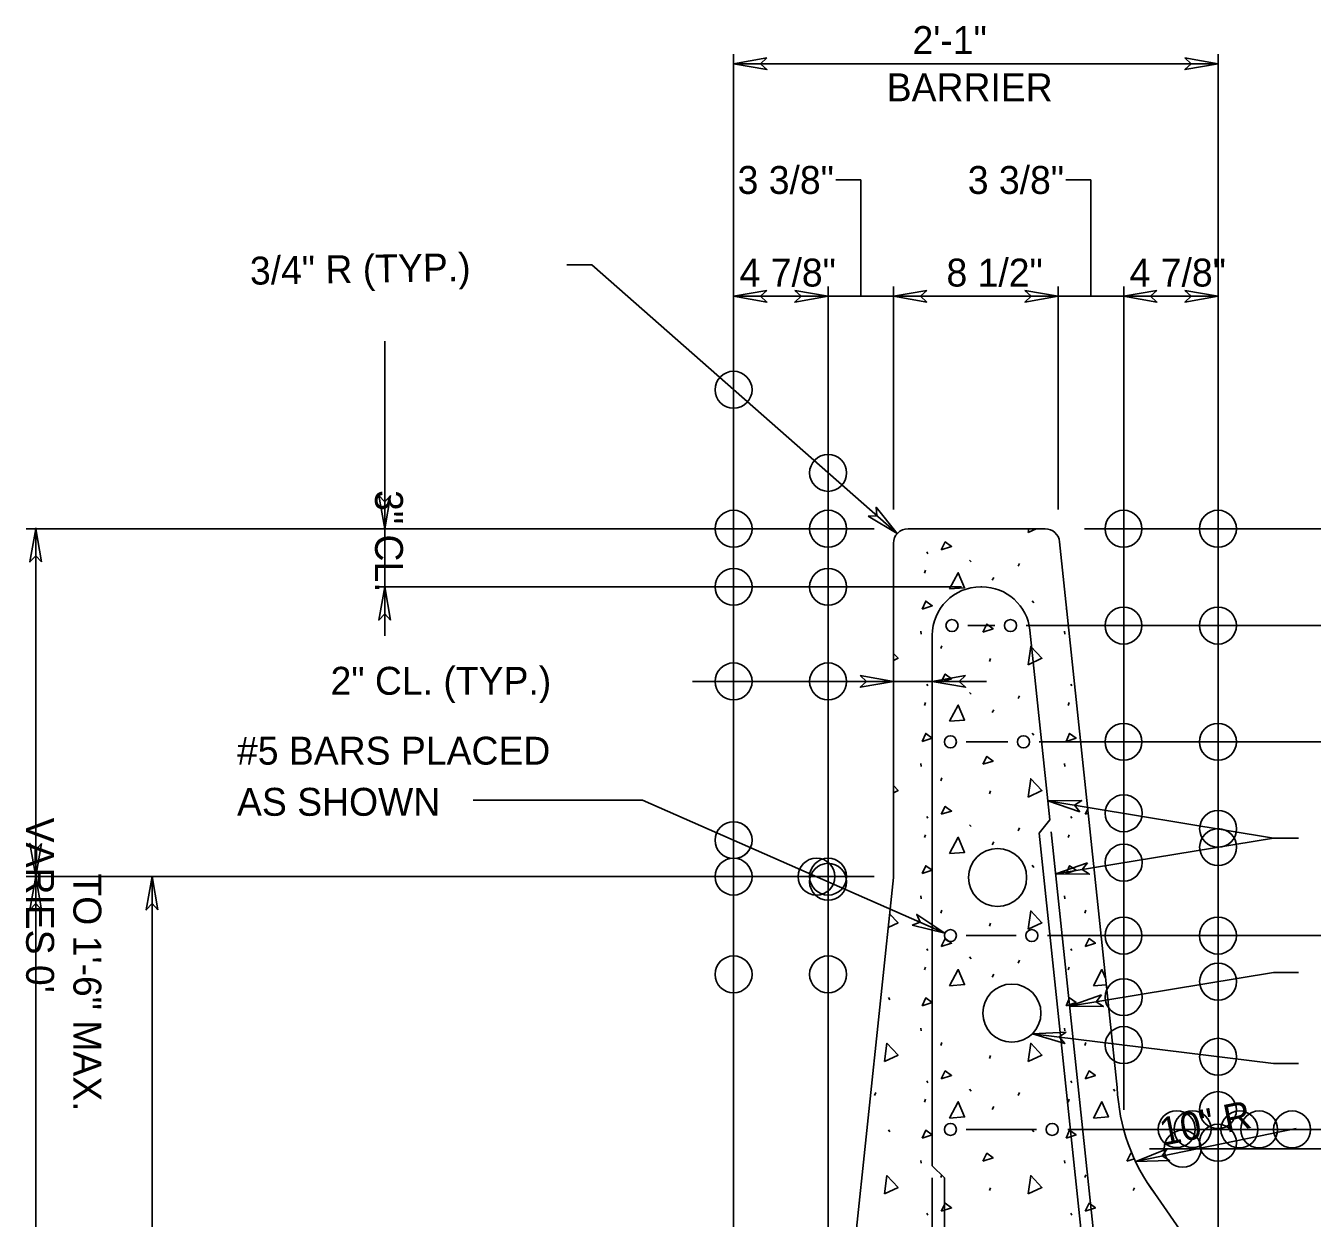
# Model space of a CAD drawing. Extents: x -26.46 to -19.21, y -3.62 to 6.25.
# Drawn here: x -25.012 to -22.246, y 3.682 to 6.246 of the extents above; entities that cross this region are included whole.
import ezdxf

# ---------------------------------------------------------------- set-up
doc = ezdxf.new("R2010")
doc.units = 0
for name, color, linetype in [('ANNO-WOUT', 7, 'Continuous'), ('CABLE_RUN', 7, 'Continuous'), ('DETL-DIMS', 7, 'Continuous'), ('DETL-PATT', 7, 'Continuous'), ('Level 10', 7, 'Continuous'), ('Level 12', 7, 'Continuous'), ('SUPR-PARA_P', 7, 'Continuous'), ('SUPR-RFRC', 7, 'Continuous')]:
    doc.layers.add(name, color=color, linetype=linetype)

msp = doc.modelspace()

# ---------------------------------------------------------------- linework, layer by layer
at = {"layer": 'ANNO-WOUT'}
for centre in [(-23.4904, 5.4635), (-23.2873, 5.2847), (-23.4904, 5.1646), (-23.2873, 5.1646), (-22.6522, 5.1646), (-22.4491, 5.1646), (-23.4904, 5.0396), (-23.2873, 5.0396), (-22.6522, 4.9563), (-22.4491, 4.9563), (-23.4904, 4.8363), (-23.2873, 4.8363), (-22.6522, 4.7063), (-22.4491, 4.7063), (-22.6518, 4.5526), (-22.4488, 4.5192), (-23.4904, 4.4949), (-23.4903, 4.4949), (-22.4488, 4.4799), (-22.6518, 4.4465), (-23.4904, 4.4164), (-23.3122, 4.4164), (-23.2873, 4.4164), (-23.2873, 4.4054), (-22.6522, 4.2896), (-22.4491, 4.2896), (-23.4904, 4.2063), (-23.2873, 4.2063), (-22.4488, 4.1906), (-22.6518, 4.1572), (-22.6518, 4.0543), (-22.4488, 4.0291), (-22.4491, 3.9144), (-22.5378, 3.8734), (-22.5037, 3.8734), (-22.403, 3.8729), (-22.3606, 3.8729), (-22.2898, 3.8729), (-22.4491, 3.8442), (-22.5251, 3.8313)]:
    msp.add_circle(centre, 0.0397, dxfattribs=at)
at = {"layer": 'CABLE_RUN'}
for centre in [(-22.9229, 4.4146), (-22.8922, 4.1229)]:
    msp.add_circle(centre, 0.0625, dxfattribs=at)
at = {"layer": 'DETL-DIMS'}
for p, q in [((-23.4904, 6.1646), (-23.419, 6.1771)), ((-23.419, 6.1771), (-23.4324, 6.1646)), ((-22.4488, 6.1646), (-22.5203, 6.1771)), ((-22.5203, 6.1771), (-22.5068, 6.1646)), ((-23.4904, 6.1646), (-23.4189, 6.1519)), ((-23.4324, 6.1646), (-23.4189, 6.1519)), ((-22.4488, 6.1646), (-22.5203, 6.1519)), ((-22.5068, 6.1646), (-22.5203, 6.1519)), ((-23.4904, 5.6646), (-23.419, 5.6771)), ((-23.419, 5.6771), (-23.4324, 5.6646)), ((-23.2873, 5.6646), (-23.3588, 5.6771)), ((-23.3588, 5.6771), (-23.3453, 5.6646)), ((-23.1467, 5.6646), (-23.0752, 5.6771)), ((-23.0752, 5.6771), (-23.0887, 5.6646)), ((-22.7925, 5.6646), (-22.864, 5.6771)), ((-22.864, 5.6771), (-22.8505, 5.6646)), ((-22.6519, 5.6646), (-22.5804, 5.6771)), ((-22.5804, 5.6771), (-22.5939, 5.6646)), ((-22.4488, 5.6646), (-22.5203, 5.6771)), ((-22.5203, 5.6771), (-22.5068, 5.6646)), ((-23.4904, 5.6646), (-23.4189, 5.6519)), ((-23.4324, 5.6646), (-23.4189, 5.6519)), ((-23.2873, 5.6646), (-23.3588, 5.6519)), ((-23.3453, 5.6646), (-23.3588, 5.6519)), ((-23.1467, 5.6646), (-23.0752, 5.6519)), ((-23.0887, 5.6646), (-23.0752, 5.6519)), ((-22.7925, 5.6646), (-22.8641, 5.6519)), ((-22.8505, 5.6646), (-22.8641, 5.6519)), ((-22.6519, 5.6646), (-22.5804, 5.6519)), ((-22.5939, 5.6646), (-22.5804, 5.6519)), ((-22.4488, 5.6646), (-22.5203, 5.6519)), ((-22.5068, 5.6646), (-22.5203, 5.6519)), ((-24.2404, 5.1646), (-24.2531, 5.2361)), ((-24.2404, 5.2226), (-24.2531, 5.2361)), ((-24.2404, 5.1646), (-24.2279, 5.2361)), ((-24.2279, 5.2361), (-24.2404, 5.2226)), ((-23.1389, 5.154), (-23.1842, 5.2108)), ((-23.1824, 5.1923), (-23.1842, 5.2108)), ((-23.2008, 5.1919), (-23.1824, 5.1923)), ((-23.1389, 5.154), (-23.2008, 5.1919)), ((-24.9904, 5.1646), (-25.0031, 5.0931)), ((-24.9904, 5.1646), (-24.9779, 5.0931)), ((-24.9904, 5.1066), (-25.0031, 5.0931)), ((-24.9779, 5.0931), (-24.9904, 5.1066)), ((-24.2404, 5.0396), (-24.2531, 4.9681)), ((-24.2404, 5.0396), (-24.2279, 4.9681)), ((-24.2404, 4.9816), (-24.2531, 4.9681)), ((-24.2279, 4.9681), (-24.2404, 4.9816)), ((-23.1467, 4.8363), (-23.2182, 4.8488)), ((-23.2182, 4.8488), (-23.2047, 4.8363)), ((-23.0634, 4.8363), (-22.9919, 4.8488)), ((-22.9919, 4.8488), (-23.0054, 4.8363)), ((-23.1467, 4.8363), (-23.2182, 4.8236)), ((-23.2047, 4.8363), (-23.2182, 4.8236)), ((-23.0634, 4.8363), (-22.9918, 4.8236)), ((-23.0054, 4.8363), (-22.9918, 4.8236)), ((-22.8146, 4.5795), (-22.742, 4.5804)), ((-22.8146, 4.5795), (-22.7461, 4.5555)), ((-22.7574, 4.57), (-22.742, 4.5804)), ((-22.7461, 4.5555), (-22.7574, 4.57)), ((-24.9904, 4.4164), (-25.0031, 4.4879)), ((-24.9904, 4.4744), (-25.0031, 4.4879)), ((-24.9904, 4.4164), (-24.9779, 4.4879)), ((-24.9779, 4.4879), (-24.9904, 4.4744)), ((-22.798, 4.4224), (-22.7295, 4.4463)), ((-22.7295, 4.4463), (-22.7408, 4.4318)), ((-22.7408, 4.4318), (-22.7254, 4.4215)), ((-24.9904, 4.4164), (-25.0031, 4.3449)), ((-24.9904, 4.4164), (-24.9779, 4.3449)), ((-24.7404, 4.4164), (-24.7531, 4.3449)), ((-24.7404, 4.4164), (-24.7279, 4.3449)), ((-22.798, 4.4224), (-22.7254, 4.4215)), ((-24.9904, 4.3584), (-25.0031, 4.3449)), ((-24.9779, 4.3449), (-24.9904, 4.3584)), ((-24.7404, 4.3584), (-24.7531, 4.3449)), ((-24.7279, 4.3449), (-24.7404, 4.3584)), ((-23.1067, 4.3122), (-23.0893, 4.3182)), ((-23.0362, 4.2948), (-23.0965, 4.3353)), ((-23.0893, 4.3182), (-23.0965, 4.3353)), ((-23.0362, 4.2948), (-23.1067, 4.3122)), ((-22.768, 4.138), (-22.6995, 4.162)), ((-22.6995, 4.162), (-22.7108, 4.1474)), ((-22.768, 4.138), (-22.6954, 4.1371)), ((-22.7108, 4.1474), (-22.6954, 4.1371)), ((-22.848, 4.0787), (-22.7755, 4.0823)), ((-22.848, 4.0787), (-22.7786, 4.0573)), ((-22.7755, 4.0823), (-22.7904, 4.0716)), ((-22.7904, 4.0716), (-22.7786, 4.0573)), ((-22.6258, 3.8042), (-22.5583, 3.8308)), ((-22.5583, 3.8308), (-22.569, 3.8158)), ((-22.6258, 3.8042), (-22.5532, 3.8061)), ((-22.569, 3.8158), (-22.5532, 3.8061))]:
    msp.add_line(p, q, dxfattribs=at)
for points in [[(-23.419, 6.1771), (-23.4904, 6.1646), (-23.4189, 6.1519), (-23.4324, 6.1646)], [(-22.5203, 6.1771), (-22.4488, 6.1646), (-22.5203, 6.1519), (-22.5068, 6.1646)], [(-23.419, 5.6771), (-23.4904, 5.6646), (-23.4189, 5.6519), (-23.4324, 5.6646)], [(-23.3588, 5.6771), (-23.2873, 5.6646), (-23.3588, 5.6519), (-23.3453, 5.6646)], [(-23.0752, 5.6771), (-23.1467, 5.6646), (-23.0752, 5.6519), (-23.0887, 5.6646)], [(-22.864, 5.6771), (-22.7925, 5.6646), (-22.8641, 5.6519), (-22.8505, 5.6646)], [(-22.5804, 5.6771), (-22.6519, 5.6646), (-22.5804, 5.6519), (-22.5939, 5.6646)], [(-22.5203, 5.6771), (-22.4488, 5.6646), (-22.5203, 5.6519), (-22.5068, 5.6646)], [(-24.2279, 5.2361), (-24.2404, 5.1646), (-24.2531, 5.2361), (-24.2404, 5.2226)], [(-23.2008, 5.1919), (-23.1389, 5.154), (-23.1842, 5.2108), (-23.1824, 5.1923)], [(-24.9779, 5.0931), (-24.9904, 5.1646), (-25.0031, 5.0931), (-24.9904, 5.1066)], [(-24.2279, 4.9681), (-24.2404, 5.0396), (-24.2531, 4.9681), (-24.2404, 4.9816)], [(-23.2182, 4.8488), (-23.1467, 4.8363), (-23.2182, 4.8236), (-23.2047, 4.8363)], [(-22.9919, 4.8488), (-23.0634, 4.8363), (-22.9918, 4.8236), (-23.0054, 4.8363)], [(-22.7461, 4.5555), (-22.8146, 4.5795), (-22.742, 4.5804), (-22.7574, 4.57)], [(-24.9779, 4.4879), (-24.9904, 4.4164), (-25.0031, 4.4879), (-24.9904, 4.4744)], [(-22.7295, 4.4463), (-22.798, 4.4224), (-22.7254, 4.4215), (-22.7408, 4.4318)], [(-24.9779, 4.3449), (-24.9904, 4.4164), (-25.0031, 4.3449), (-24.9904, 4.3584)], [(-24.7279, 4.3449), (-24.7404, 4.4164), (-24.7531, 4.3449), (-24.7404, 4.3584)], [(-23.1067, 4.3122), (-23.0362, 4.2948), (-23.0965, 4.3353), (-23.0893, 4.3182)], [(-22.6995, 4.162), (-22.768, 4.138), (-22.6954, 4.1371), (-22.7108, 4.1474)], [(-22.7755, 4.0823), (-22.848, 4.0787), (-22.7786, 4.0573), (-22.7904, 4.0716)], [(-22.5583, 3.8308), (-22.6258, 3.8042), (-22.5532, 3.8061), (-22.569, 3.8158)]]:
    msp.add_lwpolyline(points, close=True, dxfattribs=at)
at = {"layer": 'DETL-PATT'}
for p, q in [((-22.9404, 5.1635), (-22.94, 5.1646)), ((-22.8569, 5.1565), (-22.8558, 5.1646)), ((-22.8399, 5.1646), (-22.8569, 5.1565)), ((-23.0749, 5.1148), (-23.0726, 5.1109)), ((-22.9829, 5.097), (-22.9798, 5.0931)), ((-22.8786, 5.0839), (-22.8755, 5.0901)), ((-23.0803, 5.0692), (-23.078, 5.0754)), ((-22.9342, 5.0537), (-22.9311, 5.0599)), ((-22.8484, 5.0097), (-22.8453, 5.005)), ((-22.7758, 4.9919), (-22.7746, 4.9945)), ((-22.7744, 4.9923), (-22.7758, 4.9919)), ((-23.088, 4.944), (-23.0873, 4.9378)), ((-22.7789, 4.944), (-22.7781, 4.9378)), ((-23.0447, 4.9069), (-23.0424, 4.9131)), ((-22.9404, 4.879), (-22.9381, 4.8852)), ((-23.0749, 4.8303), (-23.0726, 4.8265)), ((-22.9829, 4.8126), (-22.9798, 4.8087)), ((-22.7657, 4.8303), (-22.7634, 4.8265)), ((-23.0803, 4.7847), (-23.078, 4.7909)), ((-22.8786, 4.7994), (-22.8755, 4.8056)), ((-22.7711, 4.7847), (-22.7688, 4.7909)), ((-22.9342, 4.7693), (-22.9311, 4.7755)), ((-22.8484, 4.7252), (-22.8453, 4.7206)), ((-23.088, 4.6595), (-23.0873, 4.6533)), ((-22.7789, 4.6595), (-22.7781, 4.6533)), ((-23.0447, 4.6224), (-23.0424, 4.6286)), ((-22.7356, 4.6224), (-22.7354, 4.6229)), ((-22.9404, 4.5946), (-22.9381, 4.6008)), ((-23.0749, 4.5459), (-23.0726, 4.542)), ((-22.7657, 4.5459), (-22.7634, 4.542)), ((-22.7348, 4.5505), (-22.729, 4.5622)), ((-22.728, 4.5527), (-22.7348, 4.5505)), ((-22.9829, 4.5281), (-22.9798, 4.5243)), ((-22.8786, 4.515), (-22.8755, 4.5212)), ((-23.0803, 4.5003), (-23.078, 4.5065)), ((-22.9342, 4.4848), (-22.9311, 4.491)), ((-22.7711, 4.5003), (-22.7688, 4.5065)), ((-22.8484, 4.4408), (-22.8453, 4.4361)), ((-23.088, 4.3751), (-23.0873, 4.3689)), ((-22.7789, 4.3751), (-22.7781, 4.3689)), ((-23.0447, 4.338), (-23.0424, 4.3442)), ((-22.7356, 4.338), (-22.7333, 4.3442)), ((-22.9404, 4.3102), (-22.9381, 4.3163)), ((-23.0749, 4.2615), (-23.0726, 4.2576)), ((-22.7657, 4.2615), (-22.7634, 4.2576)), ((-22.9829, 4.2437), (-22.9798, 4.2398)), ((-22.8786, 4.2305), (-22.8755, 4.2367)), ((-23.0803, 4.2159), (-23.078, 4.222)), ((-22.9342, 4.2004), (-22.9311, 4.2066)), ((-22.7711, 4.2159), (-22.7688, 4.222)), ((-22.6891, 4.1838), (-22.717, 4.1818)), ((-23.1576, 4.1563), (-23.1545, 4.1517)), ((-23.088, 4.0906), (-23.0873, 4.0845)), ((-22.7789, 4.0906), (-22.7781, 4.0845)), ((-23.0447, 4.0535), (-23.0424, 4.0597)), ((-22.7356, 4.0535), (-22.7333, 4.0597)), ((-22.9404, 4.0257), (-22.9381, 4.0319)), ((-23.0749, 3.977), (-23.0726, 3.9732)), ((-22.9829, 3.9592), (-22.9798, 3.9554)), ((-22.7657, 3.977), (-22.7634, 3.9732)), ((-22.6737, 3.9592), (-22.6706, 3.9554)), ((-23.1877, 3.9461), (-23.1847, 3.9523)), ((-23.0803, 3.9314), (-23.078, 3.9376)), ((-22.8786, 3.9461), (-22.8755, 3.9523)), ((-22.7711, 3.9314), (-22.7688, 3.9376)), ((-22.9342, 3.916), (-22.9311, 3.9221)), ((-23.1576, 3.8719), (-23.1545, 3.8673)), ((-22.8484, 3.8719), (-22.8453, 3.8673)), ((-23.088, 3.8062), (-23.0873, 3.8)), ((-22.7789, 3.8062), (-22.7781, 3.8)), ((-22.6288, 3.8099), (-22.6451, 3.8047)), ((-23.0447, 3.7691), (-23.0424, 3.7753)), ((-22.7356, 3.7691), (-22.7333, 3.7753)), ((-22.9404, 3.7413), (-22.9381, 3.7475)), ((-22.6312, 3.7413), (-22.6289, 3.7475)), ((-23.0749, 3.6926), (-23.0726, 3.6887)), ((-22.7657, 3.6926), (-22.7634, 3.6887))]:
    msp.add_line(p, q, dxfattribs=at)
for points in [[(-23.044, 5.1194), (-23.0355, 5.1364), (-23.0216, 5.1264), (-23.044, 5.1194)], [(-23.0262, 5.0352), (-23.0076, 5.07), (-22.9937, 5.0375), (-23.0262, 5.0352)], [(-23.0849, 4.9919), (-23.0772, 5.0089), (-23.0633, 4.9988), (-23.0849, 4.9919)], [(-22.9543, 4.9424), (-22.9458, 4.9594), (-22.9327, 4.9494), (-22.9543, 4.9424)], [(-23.1467, 4.8966), (-23.1367, 4.886), (-23.1467, 4.8813)], [(-22.8569, 4.8721), (-22.8515, 4.9115), (-22.8276, 4.886), (-22.8569, 4.8721)], [(-23.044, 4.835), (-23.0355, 4.852), (-23.0216, 4.8419), (-23.044, 4.835)], [(-23.0262, 4.7507), (-23.0076, 4.7855), (-22.9937, 4.7531), (-23.0262, 4.7507)], [(-23.0849, 4.7074), (-23.0772, 4.7245), (-23.0633, 4.7144), (-23.0849, 4.7074)], [(-22.7758, 4.7074), (-22.768, 4.7245), (-22.7541, 4.7144), (-22.7758, 4.7074)], [(-22.9543, 4.658), (-22.9458, 4.675), (-22.9327, 4.6649), (-22.9543, 4.658)], [(-22.8569, 4.5876), (-22.8515, 4.6271), (-22.8276, 4.6016), (-22.8569, 4.5876)], [(-23.1467, 4.6122), (-23.1367, 4.6016), (-23.1467, 4.5968)], [(-23.044, 4.5505), (-23.0355, 4.5675), (-23.0216, 4.5575), (-23.044, 4.5505)], [(-23.0262, 4.4663), (-23.0076, 4.5011), (-22.9937, 4.4686), (-23.0262, 4.4663)], [(-23.0849, 4.423), (-23.0772, 4.44), (-23.0633, 4.43), (-23.0849, 4.423)], [(-22.7758, 4.423), (-22.768, 4.44), (-22.7541, 4.43), (-22.7758, 4.423)], [(-22.8569, 4.3032), (-22.8515, 4.3426), (-22.8276, 4.3171), (-22.8569, 4.3032)], [(-23.1549, 4.3365), (-23.1367, 4.3171), (-23.158, 4.307)], [(-23.044, 4.2661), (-23.0355, 4.2831), (-23.0216, 4.2731), (-23.044, 4.2661)], [(-22.7348, 4.2661), (-22.7263, 4.2831), (-22.7124, 4.2731), (-22.7348, 4.2661)], [(-23.0262, 4.1818), (-23.0076, 4.2166), (-22.9937, 4.1842), (-23.0262, 4.1818)], [(-22.717, 4.1818), (-22.6985, 4.2166), (-22.6906, 4.1983)], [(-23.0849, 4.1386), (-23.0772, 4.1556), (-23.0633, 4.1455), (-23.0849, 4.1386)], [(-22.7758, 4.1386), (-22.768, 4.1556), (-22.7541, 4.1455), (-22.7758, 4.1386)], [(-23.1661, 4.0188), (-23.1607, 4.0582), (-23.1367, 4.0327), (-23.1661, 4.0188)], [(-22.8569, 4.0188), (-22.8515, 4.0582), (-22.8276, 4.0327), (-22.8569, 4.0188)], [(-23.044, 3.9817), (-23.0355, 3.9987), (-23.0216, 3.9886), (-23.044, 3.9817)], [(-22.7348, 3.9817), (-22.7263, 3.9987), (-22.7124, 3.9886), (-22.7348, 3.9817)], [(-23.0262, 3.8974), (-23.0076, 3.9322), (-22.9937, 3.8997), (-23.0262, 3.8974)], [(-22.717, 3.8974), (-22.6985, 3.9322), (-22.6846, 3.8997), (-22.717, 3.8974)], [(-23.0849, 3.8541), (-23.0772, 3.8711), (-23.0633, 3.8611), (-23.0849, 3.8541)], [(-22.7758, 3.8541), (-22.768, 3.8711), (-22.7541, 3.8611), (-22.7758, 3.8541)], [(-22.9543, 3.8047), (-22.9458, 3.8217), (-22.9327, 3.8116), (-22.9543, 3.8047)], [(-22.6451, 3.8047), (-22.6366, 3.8217), (-22.6325, 3.8185)], [(-23.1661, 3.7343), (-23.1607, 3.7737), (-23.1367, 3.7482), (-23.1661, 3.7343)], [(-22.8569, 3.7343), (-22.8515, 3.7737), (-22.8276, 3.7482), (-22.8569, 3.7343)], [(-23.044, 3.6972), (-23.0355, 3.7142), (-23.0216, 3.7042), (-23.044, 3.6972)], [(-22.7348, 3.6972), (-22.7263, 3.7142), (-22.7124, 3.7042), (-22.7348, 3.6972)]]:
    msp.add_lwpolyline(points, dxfattribs=at)
at = {"layer": 'Level 10'}
for p, q in [((-23.4904, 6.1854), (-23.4904, 2.8312)), ((-22.4488, 3.5812), (-22.4488, 6.1854)), ((-22.4488, 6.1646), (-23.4904, 6.1646)), ((-23.217, 5.9146), (-23.2708, 5.9146)), ((-23.217, 5.6646), (-23.217, 5.9146)), ((-22.7222, 5.9146), (-22.7761, 5.9146)), ((-22.7222, 5.6646), (-22.7222, 5.9146)), ((-23.7952, 5.7318), (-23.8491, 5.7318)), ((-23.7952, 5.7318), (-23.1389, 5.154)), ((-23.2873, 5.6854), (-23.2873, 3.1655)), ((-23.1467, 5.2062), (-23.1467, 5.6854)), ((-22.7925, 5.2062), (-22.7925, 5.6854)), ((-22.6518, 3.9153), (-22.6518, 5.6854)), ((-23.4904, 5.6646), (-23.2873, 5.6646)), ((-23.1466, 5.6646), (-23.2873, 5.6646)), ((-22.7925, 5.6646), (-23.1467, 5.6646)), ((-22.6518, 5.6646), (-22.7925, 5.6646)), ((-22.4488, 5.6646), (-22.6518, 5.6646)), ((-24.2404, 5.1646), (-24.2404, 5.5683)), ((-23.1883, 5.1646), (-25.0112, 5.1646)), ((-24.9904, 5.1668), (-24.9904, 4.4164)), ((-24.2404, 5.1646), (-24.2404, 5.0396)), ((-22.7361, 5.1646), (-20.428, 5.1646)), ((-23.0008, 5.0396), (-24.2612, 5.0396)), ((-24.2404, 5.0396), (-24.2404, 4.9341)), ((-22.987, 4.9563), (-22.9291, 4.9563)), ((-22.8614, 4.9563), (-20.928, 4.9562)), ((-23.5788, 4.8363), (-23.1467, 4.8363)), ((-23.1467, 4.8363), (-23.0633, 4.8363)), ((-22.947, 4.8363), (-23.0633, 4.8363)), ((-22.9904, 4.7063), (-22.9011, 4.7063)), ((-22.8334, 4.7063), (-20.928, 4.7063)), ((-23.6859, 4.581), (-24.0503, 4.581)), ((-23.6859, 4.581), (-23.0362, 4.2948)), ((-22.3297, 4.4995), (-22.8146, 4.5795)), ((-22.3297, 4.4995), (-22.798, 4.4224)), ((-22.3297, 4.4995), (-22.2758, 4.4995)), ((-23.1883, 4.4164), (-25.0112, 4.4164)), ((-24.9904, 4.4164), (-24.9904, 2.6646)), ((-24.7404, 3.0845), (-24.7404, 4.4164)), ((-22.9905, 4.2896), (-22.8832, 4.2896)), ((-20.928, 4.2896), (-22.8155, 4.2896)), ((-22.3297, 4.2103), (-22.768, 4.138)), ((-22.3297, 4.2103), (-22.2758, 4.2103)), ((-22.3297, 4.0143), (-22.848, 4.0787)), ((-22.3297, 4.0143), (-22.2758, 4.0143)), ((-22.9905, 3.8729), (-22.8392, 3.8729)), ((-22.7716, 3.8729), (-20.928, 3.8729)), ((-22.2807, 3.8748), (-22.6263, 3.8041)), ((-22.5963, 3.8313), (-20.678, 3.8313))]:
    msp.add_line(p, q, dxfattribs=at)
at = {"layer": 'SUPR-PARA_P'}
for p, q in [((-23.1154, 5.1646), (-22.8207, 5.1646)), ((-23.1467, 5.1333), (-23.1467, 4.4146)), ((-22.7896, 5.1366), (-22.6658, 3.9631)), ((-23.1467, 4.4146), (-23.2734, 3.2131)), ((-22.4488, 3.5396), (-22.5992, 3.7556))]:
    msp.add_line(p, q, dxfattribs=at)
for centre, radius, start, end in [((-23.1154, 5.1333), 0.0312, 90, 180), ((-22.8207, 5.1333), 0.0312, 6.0207, 90), ((-22.2496, 3.9822), 0.4167, 182.6318, 216.7526)]:
    msp.add_arc(centre, radius, start, end, dxfattribs=at)
at = {"layer": 'SUPR-RFRC'}
for p, q in [((-22.9592, 5.0396), (-22.9569, 5.0396)), ((-23.0634, 4.9354), (-23.0634, 3.7948)), ((-22.8533, 4.9463), (-22.8103, 4.5385)), ((-22.8335, 4.5099), (-22.8103, 4.5385)), ((-22.8335, 4.5099), (-22.7179, 3.4146)), ((-22.8076, 4.5126), (-22.5561, 2.1286)), ((-23.0373, 3.7687), (-23.0634, 3.7948)), ((-23.0634, 3.7687), (-23.0634, 2.1229)), ((-23.0373, 3.7687), (-23.0373, 2.6646))]:
    msp.add_line(p, q, dxfattribs=at)
for centre in [(-23.0209, 4.9563), (-22.8952, 4.9563), (-23.0243, 4.7063), (-22.8673, 4.7063), (-23.0243, 4.2896), (-22.8494, 4.2896), (-23.0243, 3.8729), (-22.8054, 3.8729)]:
    msp.add_circle(centre, 0.013, dxfattribs=at)
for centre, start, end in [((-22.9592, 4.9354), 90, 180), ((-22.9569, 4.9354), 6.0207, 90)]:
    msp.add_arc(centre, 0.1042, start, end, dxfattribs=at)

# ---------------------------------------------------------------- texts
at = {"layer": 'Level 12'}
for s, p in [('2\'-1"', (-23.1058, 6.1854)), ('BARRIER', (-23.1612, 6.0838)), ('3 3/8"', (-23.4817, 5.8846)), ('3 3/8"', (-22.9869, 5.8846)), ('4 7/8"', (-23.4775, 5.6854)), ('8 1/2"', (-23.0327, 5.6854)), ('4 7/8"', (-22.639, 5.6854)), ('2" CL. (TYP.)', (-24.3568, 4.8076)), ('#5 BARS PLACED ', (-24.5579, 4.6573)), ('AS SHOWN', (-24.5579, 4.5473))]:
    msp.add_text(s, height=0.06001, dxfattribs=at).set_placement(p)
for s, rotation, p in [('3/4" R (TYP.)', 1, (-24.5296, 5.6893)), ('3" CL.', 270, (-24.2612, 5.2476)), ("VARIES 0'", 270, (-25.0112, 4.5432)), ('TO 1\'-6" MAX.', 270, (-24.9096, 4.4233)), ('10" R', 11.5385, (-22.5677, 3.8374))]:
    msp.add_text(s, height=0.06001, rotation=rotation, dxfattribs=at).set_placement(p)

doc.saveas('drawing.dxf')
